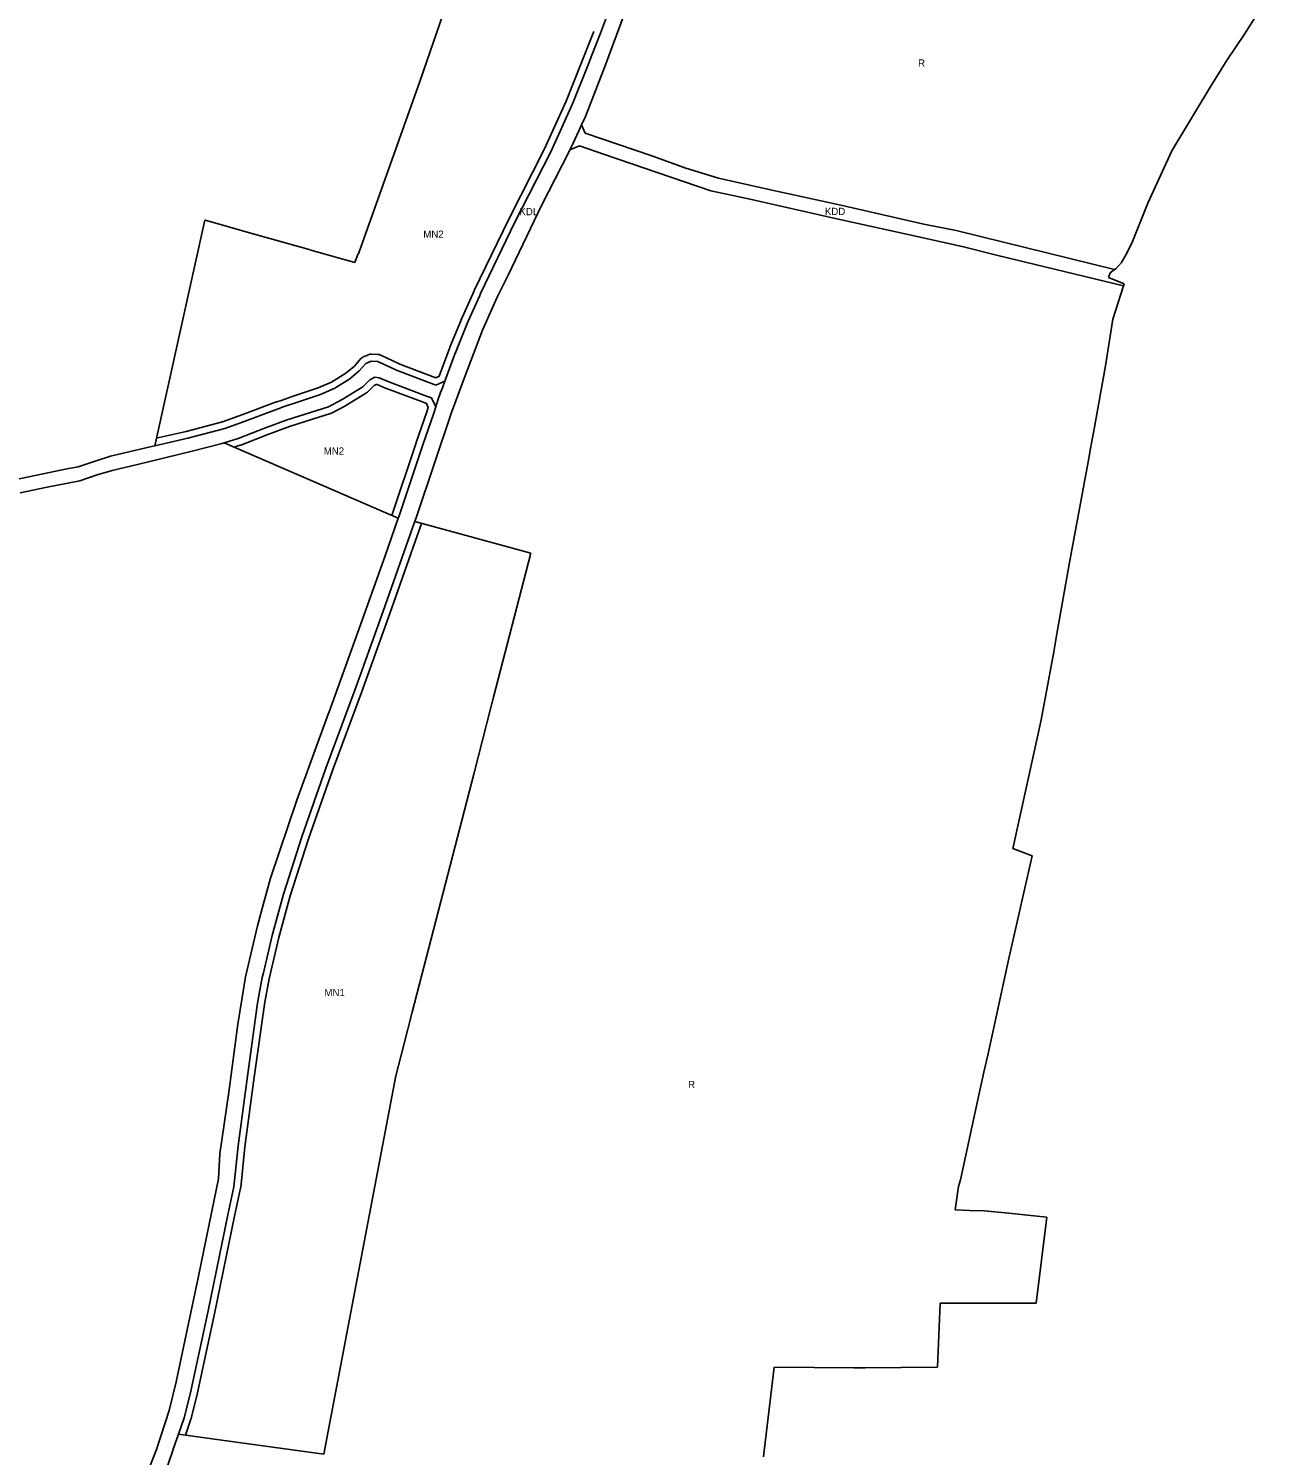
# Model space of a CAD drawing. Extents: x 7435758 to 7439981, y 5550649 to 5554049.
# Drawn here: x 7438957 to 7439847, y 5551818 to 5552845 of the extents above; entities that cross this region are included whole.
import ezdxf

# ---------------------------------------------------------------- set-up
doc = ezdxf.new("R2010")
doc.units = 0
for name, color, linetype in [('linie_rozgraniczające', 7, 'Continuous'), ('linie_zabudowy_nieprzekraczalne', 7, 'Continuous'), ('oznaczenia_przeznaczen', 7, 'Continuous')]:
    doc.layers.add(name, color=color, linetype=linetype)

msp = doc.modelspace()

# ---------------------------------------------------------------- linework, layer by layer
at = {"layer": 'linie_rozgraniczające'}
for p, q in [((7439846.9, 5552864.2), (7439832.4, 5552841.4)), ((7439255.7, 5552856), (7439238.9, 5552807.3)), ((7439373.2, 5552853.5), (7439368.8, 5552842)), ((7439372.5, 5552819.3), (7439385.2, 5552853.5)), ((7439368.8, 5552842), (7439362.6, 5552826.2)), ((7439832.4, 5552841.4), (7439820.1, 5552822.8)), ((7439362.6, 5552826.2), (7439359.4, 5552818.1)), ((7439820.1, 5552822.8), (7439807.1, 5552802.1)), ((7439359.4, 5552818), (7439348.8, 5552791.2)), ((7439358, 5552782), (7439372.5, 5552819.3)), ((7439359.4, 5552818.1), (7439359.4, 5552818)), ((7439238.9, 5552807.3), (7439194.8, 5552684)), ((7439807.1, 5552802.1), (7439780.2, 5552757.4)), ((7439348.8, 5552791.2), (7439333, 5552756.7)), ((7439355.3, 5552776.2), (7439358, 5552782)), ((7439353.2, 5552771.7), (7439348.9, 5552762.5)), ((7439355.3, 5552776.2), (7439353.2, 5552771.7)), ((7439357.9, 5552770.1), (7439355.3, 5552776.2)), ((7439348.9, 5552762.5), (7439346.8, 5552758)), ((7439346.8, 5552758), (7439353.7, 5552760.9)), ((7439353.7, 5552760.9), (7439371.7, 5552754.8)), ((7439405.9, 5552753.7), (7439357.9, 5552770.1)), ((7439333, 5552756.7), (7439307.3, 5552706)), ((7439326.5, 5552718), (7439346.1, 5552756.4)), ((7439346.1, 5552756.4), (7439346.8, 5552758)), ((7439371.7, 5552754.8), (7439448.3, 5552728.5)), ((7439430.4, 5552744.9), (7439405.9, 5552753.7)), ((7439780.2, 5552757.4), (7439762.9, 5552719.6)), ((7439453.8, 5552737.7), (7439430.4, 5552744.9)), ((7439489.1, 5552729.8), (7439453.8, 5552737.7)), ((7439541.9, 5552718.2), (7439489.1, 5552729.8)), ((7439448.3, 5552728.5), (7439475.4, 5552722.8)), ((7439475.4, 5552722.8), (7439538.9, 5552708.5)), ((7439762.9, 5552719.6), (7439751.8, 5552692.1)), ((7439302.3, 5552668), (7439326.5, 5552718)), ((7439601.6, 5552704.5), (7439541.9, 5552718.2)), ((7439084.1, 5552707.4), (7439047.9, 5552545.1)), ((7439084.3, 5552707.4), (7439084.1, 5552707.4)), ((7439120.5, 5552697.2), (7439084.3, 5552707.4)), ((7439307.3, 5552706), (7439282.5, 5552654.6)), ((7439538.9, 5552708.5), (7439601.1, 5552694.7)), ((7439624.9, 5552700), (7439601.6, 5552704.5)), ((7439658.9, 5552691.6), (7439624.9, 5552700)), ((7439159.2, 5552686.3), (7439120.5, 5552697.2)), ((7439601.1, 5552694.7), (7439630.1, 5552688.3)), ((7439630.1, 5552688.3), (7439653.9, 5552682.4)), ((7439739, 5552672), (7439658.9, 5552691.6)), ((7439751.8, 5552692.1), (7439747.7, 5552683.7)), ((7439160.3, 5552686), (7439159.2, 5552686.3)), ((7439192.1, 5552676.9), (7439160.3, 5552686)), ((7439194.4, 5552683.4), (7439192.1, 5552676.9)), ((7439194.8, 5552683.2), (7439194.4, 5552683.4)), ((7439194.8, 5552684), (7439194.8, 5552683.2)), ((7439653.9, 5552682.4), (7439745.3, 5552660.1)), ((7439747.7, 5552683.7), (7439744, 5552677)), ((7439294.5, 5552652.1), (7439302.3, 5552668)), ((7439735.8, 5552669.6), (7439734.5, 5552666.2)), ((7439739, 5552672), (7439735.8, 5552669.6)), ((7439740.2, 5552672.8), (7439739, 5552672)), ((7439744, 5552677), (7439740.2, 5552672.8)), ((7439734.5, 5552666.2), (7439745.8, 5552661.7)), ((7439745.3, 5552660.1), (7439739.9, 5552643)), ((7439745.8, 5552661.7), (7439745.3, 5552660.1)), ((7439281.9, 5552653.2), (7439273.6, 5552634.7)), ((7439282.5, 5552654.6), (7439281.9, 5552653.2)), ((7439283.9, 5552628.3), (7439294.5, 5552652.1)), ((7439739.9, 5552643), (7439737.8, 5552636.3)), ((7439272.9, 5552633.1), (7439265.1, 5552614)), ((7439270.9, 5552594.2), (7439283.9, 5552628.3)), ((7439273.6, 5552634.7), (7439272.9, 5552633.1)), ((7439737.8, 5552636.3), (7439733.7, 5552610.3)), ((7439203.8, 5552606), (7439200, 5552604.4)), ((7439208.5, 5552605.8), (7439203.8, 5552606)), ((7439263.5, 5552609.7), (7439256.7, 5552591.6)), ((7439265.1, 5552614), (7439263.5, 5552609.7)), ((7439733.7, 5552610.3), (7439732.5, 5552602.7)), ((7439195.2, 5552599), (7439188.5, 5552593.2)), ((7439200, 5552604.4), (7439195.2, 5552599)), ((7439209.1, 5552605.5), (7439208.5, 5552605.8)), ((7439222, 5552599.4), (7439209.1, 5552605.5)), ((7439250.4, 5552588.7), (7439222, 5552599.4)), ((7439732.5, 5552602.7), (7439724, 5552555.9)), ((7439177.6, 5552586.5), (7439167.4, 5552582)), ((7439188.5, 5552593.2), (7439177.6, 5552586.5)), ((7439182.9, 5552578.3), (7439197.8, 5552587.4)), ((7439197.8, 5552587.4), (7439202.9, 5552592.5)), ((7439202.9, 5552592.5), (7439206.4, 5552594.5)), ((7439206.4, 5552594.5), (7439209.5, 5552594)), ((7439209.5, 5552594), (7439216.5, 5552591)), ((7439216.5, 5552591), (7439243.7, 5552580.9)), ((7439256.7, 5552591.6), (7439250.4, 5552588.7)), ((7439253.7, 5552583.5), (7439255, 5552586.9)), ((7439255, 5552586.9), (7439256.7, 5552591.6)), ((7439261.5, 5552569.1), (7439270.9, 5552594.2)), ((7439149.3, 5552576.1), (7439141.2, 5552573.3)), ((7439167.4, 5552582), (7439149.3, 5552576.1)), ((7439173, 5552573), (7439182.9, 5552578.3)), ((7439243.7, 5552580.9), (7439247.2, 5552579.6)), ((7439247.2, 5552579.6), (7439250.3, 5552573)), ((7439250.3, 5552573), (7439251.8, 5552577.8)), ((7439251.8, 5552577.8), (7439253.7, 5552583.5)), ((7439136.7, 5552571.7), (7439110.5, 5552561.9)), ((7439141.2, 5552573.3), (7439136.7, 5552571.7)), ((7439143.4, 5552563.8), (7439160.2, 5552569)), ((7439160.2, 5552569), (7439173, 5552573)), ((7439236.6, 5552494.7), (7439261.5, 5552569.1)), ((7439248.6, 5552567.9), (7439240.9, 5552545.7)), ((7439250.3, 5552573), (7439248.6, 5552567.9)), ((7439098.3, 5552557.6), (7439071.7, 5552550.5)), ((7439110.5, 5552561.9), (7439098.3, 5552557.6)), ((7439108, 5552550.2), (7439127.6, 5552557.9)), ((7439127.6, 5552557.9), (7439143.4, 5552563.8)), ((7439724, 5552555.9), (7439723.1, 5552550.9)), ((7439045.5, 5552544.6), (7439016.2, 5552537.5)), ((7439047.9, 5552545.1), (7439045.5, 5552544.6)), ((7439048, 5552545.1), (7439047.9, 5552545.1)), ((7439071.7, 5552550.5), (7439048, 5552545.1)), ((7439074.9, 5552541.3), (7439095.6, 5552546.4)), ((7439095.6, 5552546.4), (7439098, 5552547.1)), ((7439098, 5552547.1), (7439108, 5552550.2)), ((7439098, 5552547.1), (7439223.3, 5552493)), ((7439240.9, 5552545.7), (7439223.6, 5552493.9)), ((7439723.1, 5552550.9), (7439721.7, 5552543)), ((7439005.8, 5552534.2), (7438992.9, 5552529.9)), ((7439016.2, 5552537.5), (7439005.8, 5552534.2)), ((7439036.4, 5552531.9), (7439074.9, 5552541.3)), ((7439720.2, 5552534.8), (7439706.5, 5552461)), ((7439721.7, 5552543), (7439720.2, 5552534.8)), ((7438963, 5552523.9), (7438931.4, 5552517.3)), ((7438984.6, 5552528.4), (7438963, 5552523.9)), ((7438992.9, 5552529.9), (7438984.6, 5552528.4)), ((7438994.1, 5552519.9), (7439006.5, 5552524.2)), ((7439006.5, 5552524.2), (7439017.3, 5552527.3)), ((7439017.3, 5552527.3), (7439036.4, 5552531.9)), ((7438951.1, 5552511.2), (7438970.6, 5552515.4)), ((7438970.6, 5552515.4), (7438994.1, 5552519.9)), ((7439223.3, 5552493), (7439213.8, 5552465.9)), ((7439223.6, 5552493.9), (7439223.3, 5552493)), ((7439235.2, 5552490.6), (7439236.6, 5552494.7)), ((7439212.4, 5552426.1), (7439235, 5552490.1)), ((7439235, 5552490.1), (7439235.2, 5552490.6)), ((7439318.7, 5552467.7), (7439235.2, 5552490.6)), ((7439213.8, 5552465.9), (7439193.8, 5552410.2)), ((7439291.9, 5552364), (7439318.7, 5552467.7)), ((7439318.7, 5552467.7), (7439318.7, 5552467.7)), ((7439706.5, 5552461), (7439697.5, 5552409.7)), ((7439196.1, 5552380.4), (7439212.4, 5552426.1)), ((7439193.8, 5552410.2), (7439173.5, 5552353.6)), ((7439697.5, 5552409.7), (7439695.2, 5552396.8)), ((7439695.2, 5552396.8), (7439687.5, 5552355.4)), ((7439192, 5552369.1), (7439196.1, 5552380.4)), ((7439179.6, 5552335.6), (7439192, 5552369.1)), ((7439290, 5552356.7), (7439291.9, 5552364)), ((7439172.9, 5552351.9), (7439150.2, 5552289.9)), ((7439173.5, 5552353.6), (7439172.9, 5552351.9)), ((7439277.8, 5552309.6), (7439290, 5552356.7)), ((7439687.5, 5552355.4), (7439685.9, 5552346.5)), ((7439685.9, 5552346.5), (7439666.4, 5552258.3)), ((7439171.1, 5552313), (7439179.6, 5552335.6)), ((7439153.9, 5552263.7), (7439171.1, 5552313)), ((7439233.3, 5552137.4), (7439277.8, 5552309.6)), ((7439150.2, 5552289.9), (7439131.3, 5552233.8)), ((7439140.7, 5552222.4), (7439153.9, 5552263.7)), ((7439666.4, 5552258.3), (7439665.7, 5552255.1)), ((7439679.7, 5552250), (7439662.8, 5552175.9)), ((7439665.7, 5552255.1), (7439679.7, 5552250)), ((7439131.3, 5552233.8), (7439126.1, 5552214.6)), ((7439132.5, 5552192.5), (7439140.7, 5552222.4)), ((7439126.1, 5552214.6), (7439122, 5552199.6)), ((7439122, 5552199.6), (7439113.2, 5552162.9)), ((7439126.2, 5552165.7), (7439132.5, 5552192.5)), ((7439662.8, 5552175.9), (7439647.6, 5552106.4)), ((7439125.4, 5552162.4), (7439126.2, 5552165.7)), ((7439113.2, 5552162.9), (7439110.9, 5552148)), ((7439122.2, 5552145.2), (7439125.4, 5552162.4)), ((7439110.9, 5552148), (7439107.8, 5552128.8)), ((7439121.8, 5552142.2), (7439122.2, 5552145.2)), ((7439114.7, 5552091.3), (7439121.8, 5552142.2)), ((7439227.2, 5552113.9), (7439233.3, 5552137.4)), ((7439107.8, 5552128.8), (7439101.3, 5552079.7)), ((7439221.4, 5552091.5), (7439227.2, 5552113.9)), ((7439647.6, 5552106.4), (7439644.9, 5552094.1)), ((7439644.9, 5552094.1), (7439640.3, 5552073.2)), ((7439108, 5552041.1), (7439114.7, 5552091.3)), ((7439173, 5551836.9), (7439221.4, 5552091.5)), ((7439101.3, 5552079.7), (7439094.9, 5552035.3)), ((7439640.3, 5552073.2), (7439628.1, 5552016.6)), ((7439104.9, 5552011.7), (7439108, 5552041.1)), ((7439094.9, 5552035.3), (7439093.8, 5552017.5)), ((7439093.8, 5552017.5), (7439090.8, 5552002.3)), ((7439100.5, 5551991.5), (7439104.9, 5552011.7)), ((7439626.6, 5552011.9), (7439624.1, 5551995)), ((7439628.1, 5552016.6), (7439626.6, 5552011.9)), ((7439090.8, 5552002.3), (7439079.1, 5551946.2)), ((7439086.4, 5551922.5), (7439100.5, 5551991.5)), ((7439624.1, 5551995), (7439634.6, 5551994.7)), ((7439634.6, 5551994.7), (7439645.1, 5551994.4)), ((7439645.1, 5551994.4), (7439662.9, 5551992.6)), ((7439662.9, 5551992.6), (7439680.8, 5551990.7)), ((7439680.8, 5551990.7), (7439690.2, 5551989.8)), ((7439690.2, 5551989.8), (7439682.5, 5551927.9)), ((7439079.1, 5551946.2), (7439075, 5551925.8)), ((7439075, 5551925.8), (7439063.3, 5551871.2)), ((7439073.4, 5551862.3), (7439086.4, 5551922.5)), ((7439613.4, 5551927.8), (7439611.4, 5551881.9)), ((7439682.5, 5551927.9), (7439613.4, 5551927.8)), ((7439493.8, 5551881.8), (7439490.3, 5551851.7)), ((7439522.6, 5551881.6), (7439493.8, 5551881.8)), ((7439551.3, 5551881.3), (7439522.6, 5551881.6)), ((7439559.4, 5551881.4), (7439551.3, 5551881.3)), ((7439585.4, 5551881.7), (7439559.4, 5551881.4)), ((7439611.4, 5551881.9), (7439585.4, 5551881.7)), ((7439063.3, 5551871.2), (7439058.3, 5551850.6)), ((7439069.1, 5551845.4), (7439073.4, 5551862.3)), ((7439058.3, 5551850.6), (7439049.2, 5551822.6)), ((7439490.3, 5551851.7), (7439486.7, 5551821.6)), ((7439065, 5551833.5), (7439066.7, 5551838.5)), ((7439066.7, 5551838.5), (7439069.1, 5551845.4)), ((7439169.7, 5551819.2), (7439173, 5551836.9)), ((7439061.3, 5551822.8), (7439065, 5551833.5)), ((7439065, 5551833.5), (7439097.9, 5551829)), ((7439097.9, 5551829), (7439169.7, 5551819.2)), ((7439049.2, 5551822.6), (7439039.6, 5551798.2)), ((7439049.1, 5551787.1), (7439060.8, 5551821.2)), ((7439060.8, 5551821.2), (7439061.3, 5551822.8)), ((7439486.7, 5551821.6), (7439486.2, 5551817.3))]:
    msp.add_line(p, q, dxfattribs=at)
at = {"layer": 'linie_zabudowy_nieprzekraczalne'}
for points in [[(7439048.9, 5552550.5), (7439070.5, 5552555.4), (7439096.8, 5552562.4), (7439108.8, 5552566.6), (7439135, 5552576.4), (7439135.1, 5552576.5), (7439139.6, 5552578), (7439147.7, 5552580.8), (7439165.7, 5552586.7), (7439175.3, 5552590.9), (7439185.5, 5552597.3), (7439191.7, 5552602.5), (7439196.3, 5552607.8), (7439196.8, 5552608.3), (7439197.4, 5552608.7), (7439198.1, 5552609.1), (7439201.9, 5552610.6), (7439202.6, 5552610.9), (7439203.3, 5552611), (7439204, 5552611), (7439208.7, 5552610.8), (7439209.4, 5552610.7), (7439210, 5552610.6), (7439210.6, 5552610.3), (7439211.2, 5552610), (7439223.5, 5552604.2), (7439223.7, 5552604.1), (7439224.1, 5552604), (7439224.3, 5552603.9), (7439250.2, 5552594.1), (7439252.8, 5552595.3), (7439260.4, 5552615.8), (7439260.5, 5552616), (7439268.3, 5552635), (7439268.4, 5552635.2), (7439268.4, 5552635.2), (7439277.9, 5552656.6), (7439278, 5552656.8), (7439302.8, 5552708.2), (7439302.9, 5552708.3), (7439328.5, 5552758.9), (7439344.2, 5552793.1), (7439354.7, 5552819.8), (7439364, 5552843.3)], [(7439218.7, 5552495), (7439218.9, 5552495.5), (7439236.2, 5552547.3), (7439236.2, 5552547.4), (7439243.9, 5552569.5), (7439244.9, 5552572.7), (7439243.6, 5552575.6), (7439241.9, 5552576.3), (7439214.8, 5552586.3), (7439214.6, 5552586.4), (7439208.1, 5552589.1), (7439207.3, 5552589.2), (7439205.9, 5552588.4), (7439201.3, 5552583.9), (7439201.1, 5552583.7), (7439200.4, 5552583.2), (7439185.5, 5552574), (7439185.3, 5552573.9), (7439175.3, 5552568.6), (7439174.9, 5552568.4), (7439174.5, 5552568.2), (7439161.6, 5552564.2), (7439145, 5552559), (7439129.4, 5552553.2), (7439109.9, 5552545.5), (7439109.5, 5552545.4), (7439105.1, 5552544.1)], [(7439240, 5552489.2), (7439217.1, 5552424.4), (7439217.1, 5552424.4), (7439196.8, 5552367.4), (7439196.7, 5552367.4), (7439196.7, 5552367.4), (7439175.8, 5552311.3), (7439158.7, 5552262.1), (7439145.5, 5552221), (7439137.4, 5552191.2), (7439130.3, 5552161.4), (7439127.2, 5552144.5), (7439119.6, 5552090.6), (7439112.9, 5552040.5), (7439109.9, 5552011.2), (7439109.8, 5552011), (7439109.8, 5552010.7), (7439105.4, 5551990.5), (7439091.3, 5551921.5), (7439091.3, 5551921.4), (7439078.2, 5551861.2), (7439078.2, 5551861.2), (7439078.2, 5551861.1), (7439074, 5551844.2), (7439073.9, 5551844), (7439073.8, 5551843.7), (7439071.8, 5551837.9)], [(7439071.8, 5551837.9), (7439070, 5551832.8)]]:
    msp.add_lwpolyline(points, dxfattribs=at)

# ---------------------------------------------------------------- texts
at = {"layer": 'oznaczenia_przeznaczen'}
for s, p in [('R', (7439597.5, 5552818)), ('KDL', (7439310.5, 5552711)), ('KDD', (7439530.4, 5552711.2)), ('MN2', (7439241.3, 5552694.8)), ('MN2', (7439169.6, 5552538.7)), ('MN1', (7439170.1, 5552148.9)), ('R', (7439431.9, 5552082.7))]:
    msp.add_text(s, height=5.2, dxfattribs=at).set_placement(p)

doc.saveas('drawing.dxf')
